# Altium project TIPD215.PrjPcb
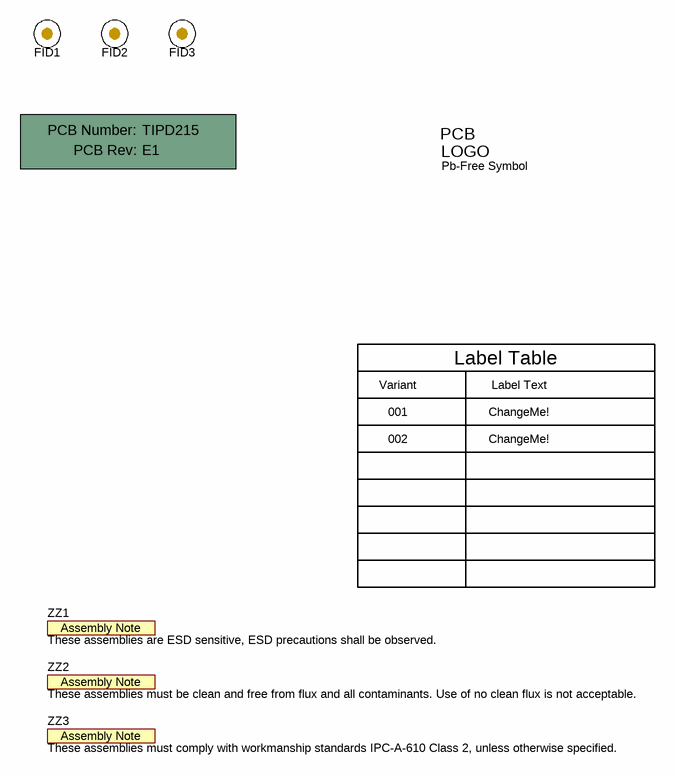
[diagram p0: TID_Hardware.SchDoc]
CopyrightYear: 2017; EVM_Orderable: N; PCB_Layout: Kevin Duke; PCB_Rev: E1; PRJ_Customer: Public Release; PRJ_Engineer: Kevin Duke; PRJ_Number: TIPD215; PRJ_Title: Less than 1W, Quad Channel, Analog Output Module with Adaptive Power Management; SCH_Rev: E1; TechSupport: http://www.ti.com/support; TID: TIPD215
3 sheets, 155 parts. Net scope: flat (ports and power ports of the same name join across sheets).
Board file: TIDPD215.PcbDoc
Sheets:
  TID_Hardware.SchDoc
  TIPD215_Device.SchDoc
  TIPD215_DAC8775SMPS.SchDoc

## Sheet TID_Hardware.SchDoc
size 431 x 279 mm; Date: Not shown in title block; ApprovedBy: Not shown in title block; CheckedBy: Not shown in title block; Author: Not shown in title block; CompanyName: Not shown in title block; Engineer: Not shown in title block; Organization: Not shown in title block; Address1: Not shown in title block; Address2: Not shown in title block; Address3: Not shown in title block; Address4: Not shown in title block; DocumentNumber: 1; Revision: Use project parameter SCH_Rev; SheetNumber: 3; SheetTotal: 3; PageSetup: Record=PageOptions¦CenterHorizontal=True¦CenterVertical=True¦PrintScale=1.00¦XCorrection=1.00¦YCorrection=1.00¦PrintKind=0¦BorderSize=5000000¦LeftOffset=0¦BottomOffset=0¦Orientation=2¦PaperLength=1000¦PaperWidth=1000¦Scale=100¦PaperSource=15¦PrintQuality=600¦MediaType=1¦DitherType=10¦PaperKind=Letter¦PrintScaleMode=1

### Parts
!PCB1  Printed Circuit Board  (value not drawn)  (mechanical)
FID1  Fiducial  [Fiducial10-20]  (value not drawn)
FID2  Fiducial  [Fiducial10-20]  (value not drawn)
FID3  Fiducial  [Fiducial10-20]  (value not drawn)
Logo2  Pb-Free Symbol  [Pb-Free_Overlay_Small]  (no BOM)
ZZ1  These assemblies are ESD sensitive, ESD precautions shall be observed.  [AssemblyNote]  (no BOM)
ZZ2  These assemblies must be clean and free from flux and all contaminants. Use of no clean flux is not acceptable.  [AssemblyNote]  (no BOM)
ZZ3  These assemblies must comply with workmanship standards IPC-A-610 Class 2, unless otherwise specified.  [AssemblyNote]  (no BOM)

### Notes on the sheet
- Variant
- Label Table
- Label Text
- 001
- 002
- ChangeMe!

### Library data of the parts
!PCB1 = PCB: Manufacturer: Any; PartNumber: TIPD215; SymbolCreator: a0412235
FID1-FID3 = Fiducial: Fiducial mark.  There is nothing to buy or mount.; SymbolCreator: codlsc
Logo2 = Pb-Free: SymbolCreator: a0412235
ZZ1-ZZ3 = AssemblyNote: SymbolCreator: codlsc

## Sheet TIPD215_Device.SchDoc
size 431 x 279 mm; Date: Not shown in title block; ApprovedBy: Not shown in title block; CheckedBy: Not shown in title block; Author: Not shown in title block; CompanyName: Not shown in title block; Engineer: Not shown in title block; Organization: Not shown in title block; Address1: Not shown in title block; Address2: Not shown in title block; Address3: Not shown in title block; Address4: Not shown in title block; DocumentNumber: 1; Revision: Use project parameter SCH_Rev; SheetNumber: 2; SheetTotal: 3; PageSetup: Record=PageOptions¦CenterHorizontal=True¦CenterVertical=True¦PrintScale=1.00¦XCorrection=1.00¦YCorrection=1.00¦PrintKind=0¦BorderSize=5000000¦LeftOffset=0¦BottomOffset=0¦Orientation=2¦PaperLength=1000¦PaperWidth=1000¦Scale=100¦PaperSource=15¦PrintQuality=600¦MediaType=1¦DitherType=10¦PaperKind=Letter¦PrintScaleMode=1
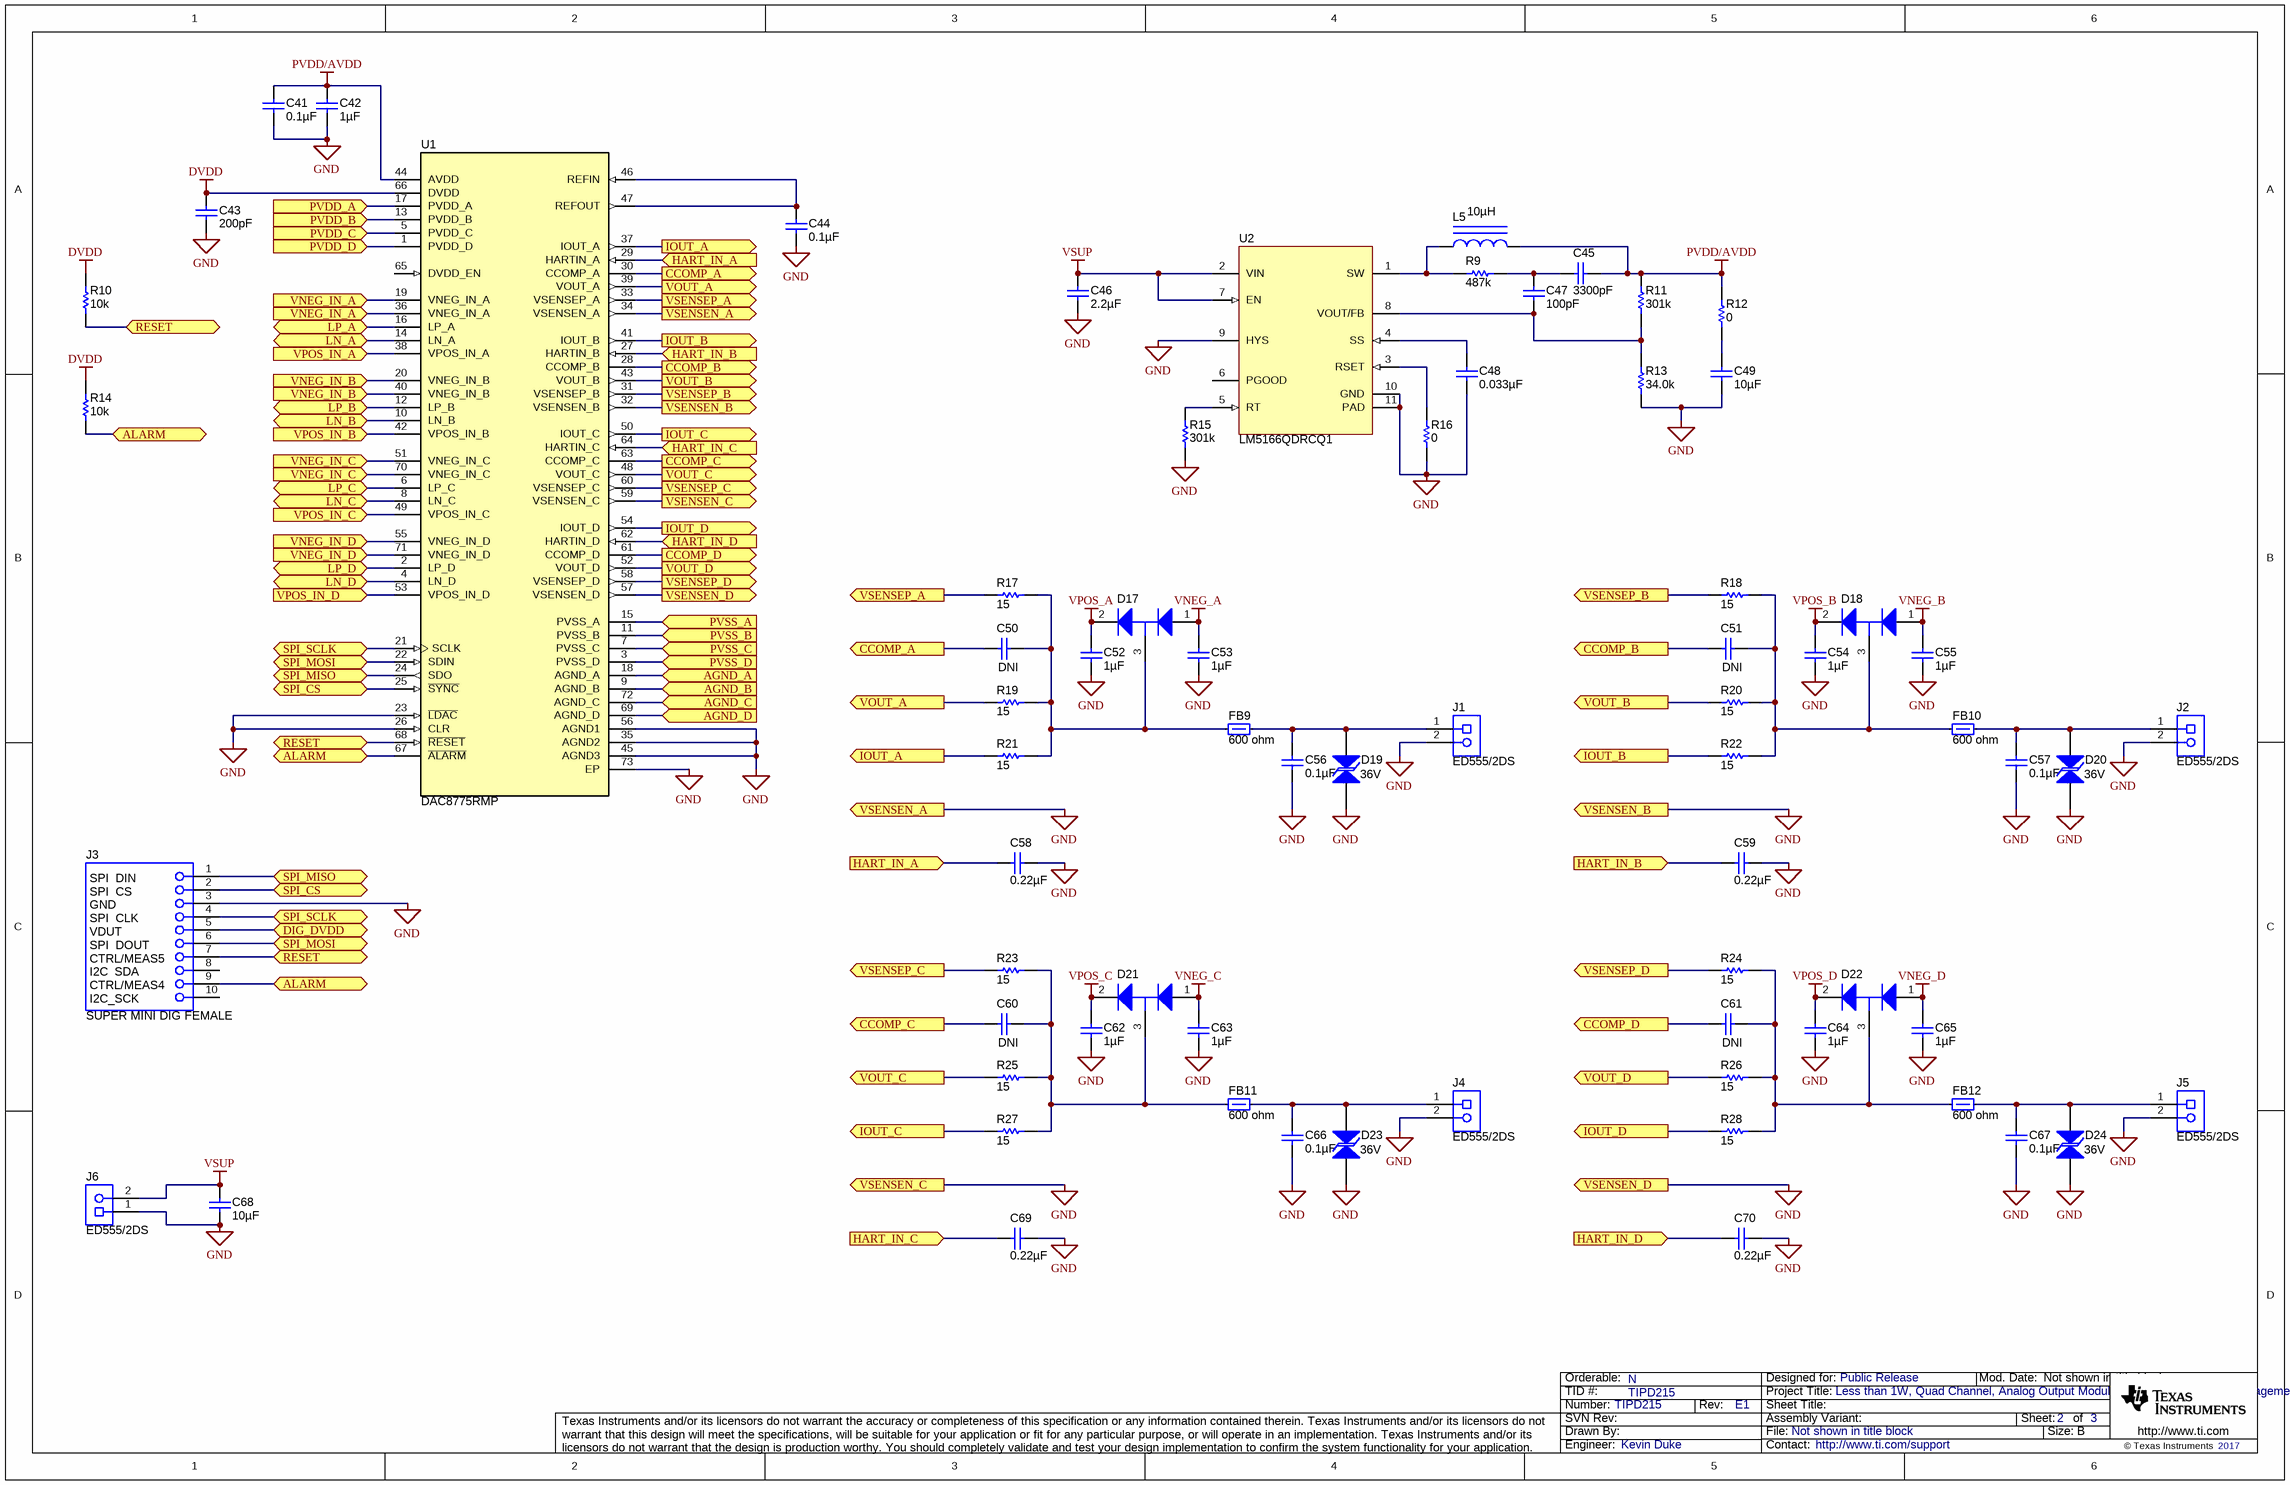
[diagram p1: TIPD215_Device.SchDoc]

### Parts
C41  ValueDisplayed: 0.1µF  [0603]  (hidden comment: GRM188R71H104KA93D)
C42  ValueDisplayed: 1µF  [0603]  (hidden comment: UMK107AB7105KA-T)
C43  ValueDisplayed: 200pF  [0603]  (hidden comment: GRM1885C1H201JA01D)
C44  ValueDisplayed: 0.1µF  [0603]  (hidden comment: GRM188R71H104KA93D)
C45  ValueDisplayed: 3300pF  [0603]  (hidden comment: 06031C332JAT2A)
C46  ValueDisplayed: 2.2µF  [1206_190]  (hidden comment: CL31B225KCHSNNE)
C47  ValueDisplayed: 100pF  [0603]  (hidden comment: GCM1885C2A101JA16D)
C48  ValueDisplayed: 0.033µF  [0603]  (hidden comment: GRM188R71H333KA61D)
C49  ValueDisplayed: 10µF  [1210_280]  (hidden comment: UMK325AB7106KM-T)
C50  DNI  [0603]
C51  DNI  [0603]
C52  ValueDisplayed: 1µF  [0603]  (hidden comment: UMK107AB7105KA-T)
C53  ValueDisplayed: 1µF  [0603]  (hidden comment: UMK107AB7105KA-T)
C54  ValueDisplayed: 1µF  [0603]  (hidden comment: UMK107AB7105KA-T)
C55  ValueDisplayed: 1µF  [0603]  (hidden comment: UMK107AB7105KA-T)
C56  ValueDisplayed: 0.1µF  [0603]  (hidden comment: GRM188R71H104KA93D)
C57  ValueDisplayed: 0.1µF  [0603]  (hidden comment: GRM188R71H104KA93D)
C58  ValueDisplayed: 0.22µF  [0603]  (hidden comment: C1608X7R1H224K080AB)
C59  ValueDisplayed: 0.22µF  [0603]  (hidden comment: C1608X7R1H224K080AB)
C60  DNI  [0603]
C61  DNI  [0603]
C62  ValueDisplayed: 1µF  [0603]  (hidden comment: UMK107AB7105KA-T)
C63  ValueDisplayed: 1µF  [0603]  (hidden comment: UMK107AB7105KA-T)
C64  ValueDisplayed: 1µF  [0603]  (hidden comment: UMK107AB7105KA-T)
C65  ValueDisplayed: 1µF  [0603]  (hidden comment: UMK107AB7105KA-T)
C66  ValueDisplayed: 0.1µF  [0603]  (hidden comment: GRM188R71H104KA93D)
C67  ValueDisplayed: 0.1µF  [0603]  (hidden comment: GRM188R71H104KA93D)
C68  ValueDisplayed: 10µF  [1210_280]  (hidden comment: UMK325AB7106KM-T)
C69  ValueDisplayed: 0.22µF  [0603]  (hidden comment: C1608X7R1H224K080AB)
C70  ValueDisplayed: 0.22µF  [0603]  (hidden comment: C1608X7R1H224K080AB)
D17  BAV99-7-F  [SOT-23]  (value not drawn)
D18  BAV99-7-F  [SOT-23]  (value not drawn)
D19  value 36V  [SOD-323-Bi]  (hidden comment: CDSOD323-T36SC)
D20  value 36V  [SOD-323-Bi]  (hidden comment: CDSOD323-T36SC)
D21  BAV99-7-F  [SOT-23]  (value not drawn)
D22  BAV99-7-F  [SOT-23]  (value not drawn)
D23  value 36V  [SOD-323-Bi]  (hidden comment: CDSOD323-T36SC)
D24  value 36V  [SOD-323-Bi]  (hidden comment: CDSOD323-T36SC)
FB9  value 600 ohm  [1210_280]  (hidden comment: FBMH3225HM601NT)
FB10  value 600 ohm  [1210_280]  (hidden comment: FBMH3225HM601NT)
FB11  value 600 ohm  [1210_280]  (hidden comment: FBMH3225HM601NT)
FB12  value 600 ohm  [1210_280]  (hidden comment: FBMH3225HM601NT)
J1  ED555/2DS  [TERM_BLK_ED555-2DS]
J2  ED555/2DS  [TERM_BLK_ED555-2DS]
J3  SUPER MINI DIG FEMALE  [CONN_851-43-010-20-001000]
J4  ED555/2DS  [TERM_BLK_ED555-2DS]
J5  ED555/2DS  [TERM_BLK_ED555-2DS]
J6  ED555/2DS  [TERM_BLK_ED555-2DS]
L5  ValueDisplayed: 10µH  [WE-LQS_6045]  (hidden comment: 74404064100)
R9  ValueDisplayed: 487k  [0603]  (hidden comment: CRCW0603487KFKEA)
R10  value 10k  [0603]  (hidden comment: CRCW060310K0JNEA)
R11  ValueDisplayed: 301k  [0603]  (hidden comment: CRCW0603301KFKEA)
R12  ValueDisplayed: 0  [0603]  (hidden comment: CRCW06030000Z0EA)
R13  ValueDisplayed: 34.0k  [0603]  (hidden comment: CRCW060334K0FKEA)
R14  value 10k  [0603]  (hidden comment: CRCW060310K0JNEA)
R15  ValueDisplayed: 301k  [0603]  (hidden comment: CRCW0603301KFKEA)
R16  ValueDisplayed: 0  [0603]  (hidden comment: CRCW06030000Z0EA)
R17  value 15  [0603]  (hidden comment: CRCW060315R0JNEA)
R18  value 15  [0603]  (hidden comment: CRCW060315R0JNEA)
R19  value 15  [0603]  (hidden comment: CRCW060315R0JNEA)
R20  value 15  [0603]  (hidden comment: CRCW060315R0JNEA)
R21  value 15  [0603]  (hidden comment: CRCW060315R0JNEA)
R22  value 15  [0603]  (hidden comment: CRCW060315R0JNEA)
R23  value 15  [0603]  (hidden comment: CRCW060315R0JNEA)
R24  value 15  [0603]  (hidden comment: CRCW060315R0JNEA)
R25  value 15  [0603]  (hidden comment: CRCW060315R0JNEA)
R26  value 15  [0603]  (hidden comment: CRCW060315R0JNEA)
R27  value 15  [0603]  (hidden comment: CRCW060315R0JNEA)
R28  value 15  [0603]  (hidden comment: CRCW060315R0JNEA)
U1  DAC8775RMP  [RMP0072A]
U2  LM5166QDRCQ1  [DRC0010J]

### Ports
AGND_A (in), AGND_B (in), AGND_C (in), AGND_D (in), ALARM, CCOMP_A (out), CCOMP_B (out), CCOMP_C (out), CCOMP_D (out), DIG_DVDD, HART_IN_A (in), HART_IN_B (in), HART_IN_C (in), HART_IN_D (in), IOUT_A (out), IOUT_B (out), IOUT_C (out), IOUT_D (out), LN_A (bidir), LN_B (bidir), LN_C (bidir), LN_D (bidir), LP_A (bidir), LP_B (bidir), LP_C (bidir), LP_D (bidir), PVDD_A (in), PVDD_B (in), PVDD_C (in), PVDD_D (in), PVSS_A (in), PVSS_B (in), PVSS_C (in), PVSS_D (in), RESET, SPI_CS, SPI_MISO, SPI_MOSI, SPI_SCLK, VNEG_IN_A (in), VNEG_IN_B (in), VNEG_IN_C (in), VNEG_IN_D (in), VOUT_A (out), VOUT_B (out), VOUT_C (out), VOUT_D (out), VPOS_IN_A (in), VPOS_IN_B (in), VPOS_IN_C (in), VPOS_IN_D (in), VSENSEN_A (out), VSENSEN_B (out), VSENSEN_C (out), VSENSEN_D (out), VSENSEP_A (out), VSENSEP_B (out), VSENSEP_C (out), VSENSEP_D (out)

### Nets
DVDD: C43.1 R10.2 R14.2 U1.66(DVDD)
GND: C41.1 C42.1 C43.2 C44.2 C46.2 C48.2 C49.2 C52.1 C53.1 C54.1 C55.1 C56.2 C57.2 C58.1 C59.1 C62.1 C63.1 C64.1 C65.1 C66.2 C67.2 C68.2 C69.1 C70.1 D19.1 D20.1 D23.1 D24.1 J1.2 J2.2 J3.3 J4.2 J5.2 J6.1 R13.1 R15.1 R16.1 U1.3(PVSS_D) U1.7(PVSS_C) U1.9(AGND_B) U1.11(PVSS_B) U1.15(PVSS_A) U1.18(AGND_A) U1.23(~{LDAC}) U1.26(CLR) U1.32(VSENSEN_B) U1.34(VSENSEN_A) U1.35(AGND2) U1.45(AGND3) U1.56(AGND1) U1.57(VSENSEN_D) U1.59(VSENSEN_C) U1.69(AGND_D) U1.72(AGND_C) U1.73(EP) U2.9(HYS) U2.10(GND) U2.11(PAD) ; port VSENSEN_A, port VSENSEN_B, port VSENSEN_C, port VSENSEN_D, port AGND_A, port PVSS_A, port AGND_B, port PVSS_B, port AGND_C, port PVSS_C, port AGND_D, port PVSS_D
PVDD/AVDD: C41.2 C42.2 C45.1 L5.2 R11.2 R12.2 U1.1(PVDD_D) U1.5(PVDD_C) U1.13(PVDD_B) U1.17(PVDD_A) U1.44(AVDD) ; port PVDD_A, port PVDD_B, port PVDD_C, port PVDD_D
VNEG_A: C53.2 D17.1(A) U1.19(VNEG_IN_A) U1.36(VNEG_IN_A) ; port VNEG_IN_A
VNEG_B: C55.2 D18.1(A) U1.20(VNEG_IN_B) U1.40(VNEG_IN_B) ; port VNEG_IN_B
VNEG_C: C63.2 D21.1(A) U1.51(VNEG_IN_C) U1.70(VNEG_IN_C) ; port VNEG_IN_C
VNEG_D: C65.2 D22.1(A) U1.55(VNEG_IN_D) U1.71(VNEG_IN_D) ; port VNEG_IN_D
VPOS_A: C52.2 D17.2(K) U1.38(VPOS_IN_A) ; port VPOS_IN_A
VPOS_B: C54.2 D18.2(K) U1.42(VPOS_IN_B) ; port VPOS_IN_B
VPOS_C: C62.2 D21.2(K) U1.49(VPOS_IN_C) ; port VPOS_IN_C
VPOS_D: C64.2 D22.2(K) U1.53(VPOS_IN_D) ; port VPOS_IN_D
VSUP: C46.1 C68.1 J6.2 U2.2(VIN) U2.7(EN)
ALARM: J3.9 R14.1 U1.67(~{ALARM}) ; port ALARM
CCOMP_A: C50.2 U1.30(CCOMP_A) ; port CCOMP_A
CCOMP_B: C51.2 U1.28(CCOMP_B) ; port CCOMP_B
CCOMP_C: C60.2 U1.63(CCOMP_C) ; port CCOMP_C
CCOMP_D: C61.2 U1.61(CCOMP_D) ; port CCOMP_D
DIG_DVDD: J3.5 ; port DIG_DVDD
HART_IN_A: C58.2 U1.29(HARTIN_A) ; port HART_IN_A
HART_IN_B: C59.2 U1.27(HARTIN_B) ; port HART_IN_B
HART_IN_C: C69.2 U1.64(HARTIN_C) ; port HART_IN_C
HART_IN_D: C70.2 U1.62(HARTIN_D) ; port HART_IN_D
IOUT_A: R21.1 U1.37(IOUT_A) ; port IOUT_A
IOUT_B: R22.1 U1.41(IOUT_B) ; port IOUT_B
IOUT_C: R27.1 U1.50(IOUT_C) ; port IOUT_C
IOUT_D: R28.1 U1.54(IOUT_D) ; port IOUT_D
LN_A: U1.14(LN_A) ; port LN_A
LN_B: U1.10(LN_B) ; port LN_B
LN_C: U1.8(LN_C) ; port LN_C
LN_D: U1.4(LN_D) ; port LN_D
LP_A: U1.16(LP_A) ; port LP_A
LP_B: U1.12(LP_B) ; port LP_B
LP_C: U1.6(LP_C) ; port LP_C
LP_D: U1.2(LP_D) ; port LP_D
RESET: J3.7 R10.1 U1.68(~{RESET}) ; port RESET
SPI_CS: J3.2 U1.25(~{SYNC}) ; port SPI_CS
SPI_MISO: J3.1 U1.24(SDO) ; port SPI_MISO
SPI_MOSI: J3.6 U1.22(SDIN) ; port SPI_MOSI
SPI_SCLK: J3.4 U1.21(SCLK) ; port SPI_SCLK
VOUT_A: R19.1 U1.39(VOUT_A) ; port VOUT_A
VOUT_B: R20.1 U1.43(VOUT_B) ; port VOUT_B
VOUT_C: R25.1 U1.48(VOUT_C) ; port VOUT_C
VOUT_D: R26.1 U1.52(VOUT_D) ; port VOUT_D
VSENSEP_A: R17.1 U1.33(VSENSEP_A) ; port VSENSEP_A
VSENSEP_B: R18.1 U1.31(VSENSEP_B) ; port VSENSEP_B
VSENSEP_C: R23.1 U1.60(VSENSEP_C) ; port VSENSEP_C
VSENSEP_D: R24.1 U1.58(VSENSEP_D) ; port VSENSEP_D
NetC44_1: C44.1 U1.46(REFIN) U1.47(REFOUT)
NetC45_2: C45.2 C47.1 R9.2
NetC47_2: C47.2 R11.1 R13.2 U2.8(VOUT/FB)
NetC48_1: C48.1 U2.4(SS)
NetC49_1: C49.1 R12.1
NetC50_1: C50.1 D17.3(C) FB9.1 R17.2 R19.2 R21.2
NetC51_1: C51.1 D18.3(C) FB10.1 R18.2 R20.2 R22.2
NetC56_1: C56.1 D19.2 FB9.2 J1.1
NetC57_1: C57.1 D20.2 FB10.2 J2.1
NetC60_1: C60.1 D21.3(C) FB11.1 R23.2 R25.2 R27.2
NetC61_1: C61.1 D22.3(C) FB12.1 R24.2 R26.2 R28.2
NetC66_1: C66.1 D23.2 FB11.2 J4.1
NetC67_1: C67.1 D24.2 FB12.2 J5.1
NetL5_1: L5.1 R9.1 U2.1(SW)
NetR15_2: R15.2 U2.5(RT)
NetR16_2: R16.2 U2.3(RSET)

Not connected (* = marked no-connect by the designer): J3 8 10; U1 65(DVDD_EN); U2 6(PGOOD)

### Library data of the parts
C41 C44 C56 C57 C66 C67 = GRM188R71H104KA93D: CAP, CERM, 0.1uF, 50V, +/-10%, X7R, 0603; Manufacturer: MuRata; Polarized: N; CompType: Capacitor; U/M: EA; Cap_F: 0.0000001; Tolerance_%: 10; Value1: Unknown; VDC_V: 50; TaMin_C: -55; TaMax_C: 125
C42 C52-C55 C62-C65 = UMK107AB7105KA-T: CAP, CERM, 1uF, 50V, +/-10%, X7R, 0603; Manufacturer: Taiyo Yuden; Polarized: N; CompType: Capacitor; U/M: EA; Cap_F: 0.000001; Tolerance_%: 10; Value1: Unknown; VDC_V: 50; TaMin_C: -55; TaMax_C: 125
C43 = GRM1885C1H201JA01D: CAP, CERM, 200pF, 50V, +/-5%, C0G/NP0, 0603; Manufacturer: MuRata; Polarized: N; CompType: Capacitor; U/M: EA; Cap_F: 0.0000000002; Tolerance_%: 5; Value1: Unknown; VDC_V: 50; TaMin_C: -55; TaMax_C: 125
C45 = 06031C332JAT2A: CAP, CERM, 3300 pF, 100 V, +/- 5%, X7R, 0603; Manufacturer: AVX; Polarized: N; CompType: Capacitor; Value: 3300pF; U/M: EA; Cap_F: 0.0000000033; Tolerance_%: 5; ESR_ohm: 0.159; Value1: 0.159 ohm; VDC_V: 100; Value2: 100V; TaMin_C: -55; TaMax_C: 125; SizeArea_mm2: 1.28; SizeAreaWB_mm2: 4.68; SizeX_mm: 1.6; SizeY_mm: 0.8; SizeZ_mm: 1; AEC Category: Q200
C46 = CL31B225KCHSNNE: CAP, CERM, 2.2 µF, 100 V, +/- 10%, X7R, 1206_190; Manufacturer: Samsung Electro-Mechanics; Polarized: N; CompType: Capacitor; Value: 2.2uF; U/M: EA; Cap_F: 0.0000022; Tolerance_%: 10; Value1: Unknown; VDC_V: 100; Value2: 100V; TaMin_C: -55; TaMax_C: 125; Cap_Case: 1206; SizeArea_mm2: 5.12; SizeAreaWB_mm2: 10.92; SizeX_mm: 3.2; SizeY_mm: 1.6; SizeZ_mm: 1.9; AEC Category: Q200
C47 = GCM1885C2A101JA16D: CAP, CERM, 100 pF, 100 V, +/- 5%, C0G/NP0, AEC-Q200 Grade 1, 0603; Manufacturer: MuRata; Polarized: N; CompType: Capacitor; Value: 100pF; U/M: EA; Cap_F: 0.0000000001; Tolerance_%: 5; Value1: Unknown; VDC_V: 100; Value2: 100V; TaMin_C: -55; TaMax_C: 125; SizeArea_mm2: 1.28; SizeAreaWB_mm2: 4.68; SizeX_mm: 1.6; SizeY_mm: 0.8; SizeZ_mm: 1; AEC Category: Q200; AEC Qualified: Y
C48 = GRM188R71H333KA61D: CAP, CERM, 0.033 µF, 50 V, +/- 10%, X7R, 0603; Manufacturer: MuRata; Polarized: N; CompType: Capacitor; Value: 0.033uF; U/M: EA; Cap_F: 0.000000033; Tolerance_%: 10; Value1: Unknown; VDC_V: 50; Value2: 50V; TaMin_C: -55; TaMax_C: 125; SizeArea_mm2: 1.28; SizeAreaWB_mm2: 4.68; SizeX_mm: 1.6; SizeY_mm: 0.8; SizeZ_mm: 1; AEC Category: Q200
C49 C68 = UMK325AB7106KM-T: CAP, CERM, 10 µF, 50 V, +/- 10%, X7R, 1210; Manufacturer: Taiyo Yuden; Polarized: N; CompType: Capacitor; Value: 10uF; U/M: EA; Cap_F: 0.00001; Tolerance_%: 10; Value1: Unknown; VDC_V: 50; Value2: 50V; TaMin_C: -55; TaMax_C: 125; Cap_Case: 1210; SizeArea_mm2: 8; SizeAreaWB_mm2: 14.7; SizeX_mm: 3.2; SizeY_mm: 2.5; SizeZ_mm: 2.8; AEC Category: Q200
C50 C51 C60 C61 = GRM1885C1H222JA01D
C58 C59 C69 C70 = C1608X7R1H224K080AB: CAP, CERM, 0.22 µF, 50 V, +/- 10%, X7R, 0603; Manufacturer: TDK; Polarized: N; CompType: Capacitor; Value: 0.22uF; U/M: EA; Cap_F: 0.00000022; Tolerance_%: 10; ESR_ohm: 0.021699; Value1: 0.021699 ohm; VDC_V: 50; Value2: 50V; IRMS_A: 1.12496; TaMin_C: -55; TaMax_C: 125; SizeArea_mm2: 1.28; SizeAreaWB_mm2: 4.68; SizeX_mm: 1.6; SizeY_mm: 0.8; SizeZ_mm: 1; AEC Category: Q200
D17 D18 D21 D22 = BAV99-7-F: Diode, Switching, 75V, 0.3A, SOT-23; Manufacturer: Diodes Inc.; U/M: EA; Vf_V: 1.25; Value2: 1.25V; Io_A: 0.3; Vr_V: 75; TJmax_C: 150; RJC_CperW: 357
D19 D20 D23 D24 = CDSOD323-T36SC: Diode, TVS, Bi, 36V, 400W, SOD323, 2-Leads, Body 1.9x1.45mm, No Polarity Mark; Manufacturer: Bourns; U/M: EA; Power_W: 400; Vr_V: 36
FB9-FB12 = FBMH3225HM601NT: Ferrite Bead, 600 ohm @ 100 MHz, 3 A, 1210; Manufacturer: Taiyo Yuden; Imax_A: 3; DCR_ohm: 0.042; Value1: 0.042 ohm; Value2: 3A; ZTyp@100MHz_Ohm: 600
J1 J2 J4-J6 = ED555/2DS: Terminal Block, 3.5mm Pitch, 2x1, TH; Manufacturer: On-Shore Technology; SymbolCreator: a0412235; Pitch_mm: 3.5; Gender: Female; Shrouded: N; Row_Count: 1; ContactFinish: Brass; Current_A: 6; Voltage_V: 150; Cert_CULUS: Y
J3 = 851-43-010-20-001000: Receptacle, 50mil 10x1, R/A, TH; Manufacturer: Mill-Max; SymbolCreator: a0411947; U/M: EA
L5 = 74404064100: Inductor, Wirewound, Ferrite, 10 µH, 2.45 A, 0.048 ohm, SMD; Manufacturer: Wurth Elektronik; Value: 10uH; Ind_H: 10.0E-6; Imax_A: 2.45; Irms: 2.45A @ 40C rise; Isat: 3.5A @ 30% inductance drop; DCR_ohm: 0.048; Value2: 2.45A; AEC Category: Q200
R9 = CRCW0603487KFKEA: RES, 487 k, 1%, 0.1 W, 0603; Manufacturer: Vishay-Dale; CompType: Resistor; Value: 487k; Res_ohm: 487000; Tolerance_%: 1; Power_W: 0.1; Value2: 0.1W; VDC_V: 75; TempCo: 100 ppm/C; SizeArea_mm2: 1.28; SizeX_mm: 1.6; SizeY_mm: 0.8; EIA_Code: E96; U/M: EA; AEC Category: Q200
R10 R14 = CRCW060310K0JNEA: RES, 10k ohm, 5%, 0.1W, 0603; Manufacturer: Vishay-Dale; CompType: Resistor; Res_ohm: 10000; Value_Code: 10k0; Tolerance_%: 5; Power_W: 0.1; VDC_V: 75; TempCo: 200 ppm/C; EIA_Code: E24; U/M: EA
R11 R15 = CRCW0603301KFKEA: RES, 301 k, 1%, 0.1 W, 0603; Manufacturer: Vishay-Dale; CompType: Resistor; Value: 301k; Res_ohm: 301000; Tolerance_%: 1; Power_W: 0.1; Value2: 0.1W; VDC_V: 75; TempCo: 100 ppm/C; SizeArea_mm2: 1.28; SizeX_mm: 1.6; SizeY_mm: 0.8; EIA_Code: E96; U/M: EA; AEC Category: Q200
R12 R16 = CRCW06030000Z0EA: RES, 0, 5%, 0.1 W, 0603; Manufacturer: Vishay-Dale; CompType: Resistor; Value: 0; Value_Code: 0000; Tolerance_%: 5; Power_W: 0.1; Value2: 0.1W; VDC_V: 75; TempCo: 200 ppm/C; SizeArea_mm2: 1.28; SizeX_mm: 1.6; SizeY_mm: 0.8; SizeZ_mm: 1; EIA_Code: E24; U/M: EA; AEC Category: Q200
R13 = CRCW060334K0FKEA: RES, 34.0 k, 1%, 0.1 W, 0603; Manufacturer: Vishay-Dale; CompType: Resistor; Value: 34.0k; Res_ohm: 34000; Value_Code: 34k0; Tolerance_%: 1; Power_W: 0.1; Value2: 0.1W; VDC_V: 75; TempCo: 100 ppm/C; SizeArea_mm2: 1.28; SizeX_mm: 1.6; SizeY_mm: 0.8; EIA_Code: E96; U/M: EA; AEC Category: Q200
R17-R28 = CRCW060315R0JNEA: RES, 15 ohm, 5%, 0.1W, 0603; Manufacturer: Vishay-Dale; CompType: Resistor; Value_Code: 15R0; Tolerance_%: 5; Power_W: 0.1; VDC_V: 75; TempCo: 200 ppm/C; EIA_Code: E24; U/M: EA
U1 = DAC8775RMP: Quad-Channel, 16-Bit Programmable Current Output and Voltage Output Digital-to-Analog Converter with Adaptive Power Management, RMP0072A; Manufacturer: Texas Instruments; SymbolCreator: Altium; SizeArea_mm2: 100; SizeAreaWB_mm2: 144; SizeX_mm: 10; SizeZ_mm: 1; CompType: IC; U/M: EA
U2 = LM5166QDRCQ1: 3.5-V to 65-V Input, 500-mA Output, Ultra-Low Quiescent Synchronous Step-Down DC/DC Voltage Regulator, DRC0010J; Manufacturer: Texas Instruments; SymbolCreator: a0411947; SizeArea_mm2: 9; SizeAreaWB_mm2: 16; SizeX_mm: 3; SizeZ_mm: 1; CompType: IC; U/M: EA

## Sheet TIPD215_DAC8775SMPS.SchDoc
size 431 x 279 mm; Date: Not shown in title block; ApprovedBy: Not shown in title block; CheckedBy: Not shown in title block; Author: Not shown in title block; CompanyName: Not shown in title block; Engineer: Not shown in title block; Organization: Not shown in title block; Address1: Not shown in title block; Address2: Not shown in title block; Address3: Not shown in title block; Address4: Not shown in title block; DocumentNumber: 1; Revision: Use project parameter SCH_Rev; SheetNumber: 2; SheetTotal: 3; PageSetup: Record=PageOptions¦CenterHorizontal=True¦CenterVertical=True¦PrintScale=1.00¦XCorrection=1.00¦YCorrection=1.00¦PrintKind=0¦BorderSize=5000000¦LeftOffset=0¦BottomOffset=0¦Orientation=2¦PaperLength=1000¦PaperWidth=1000¦Scale=100¦PaperSource=15¦PrintQuality=600¦MediaType=1¦DitherType=10¦PaperKind=Letter¦PrintScaleMode=1
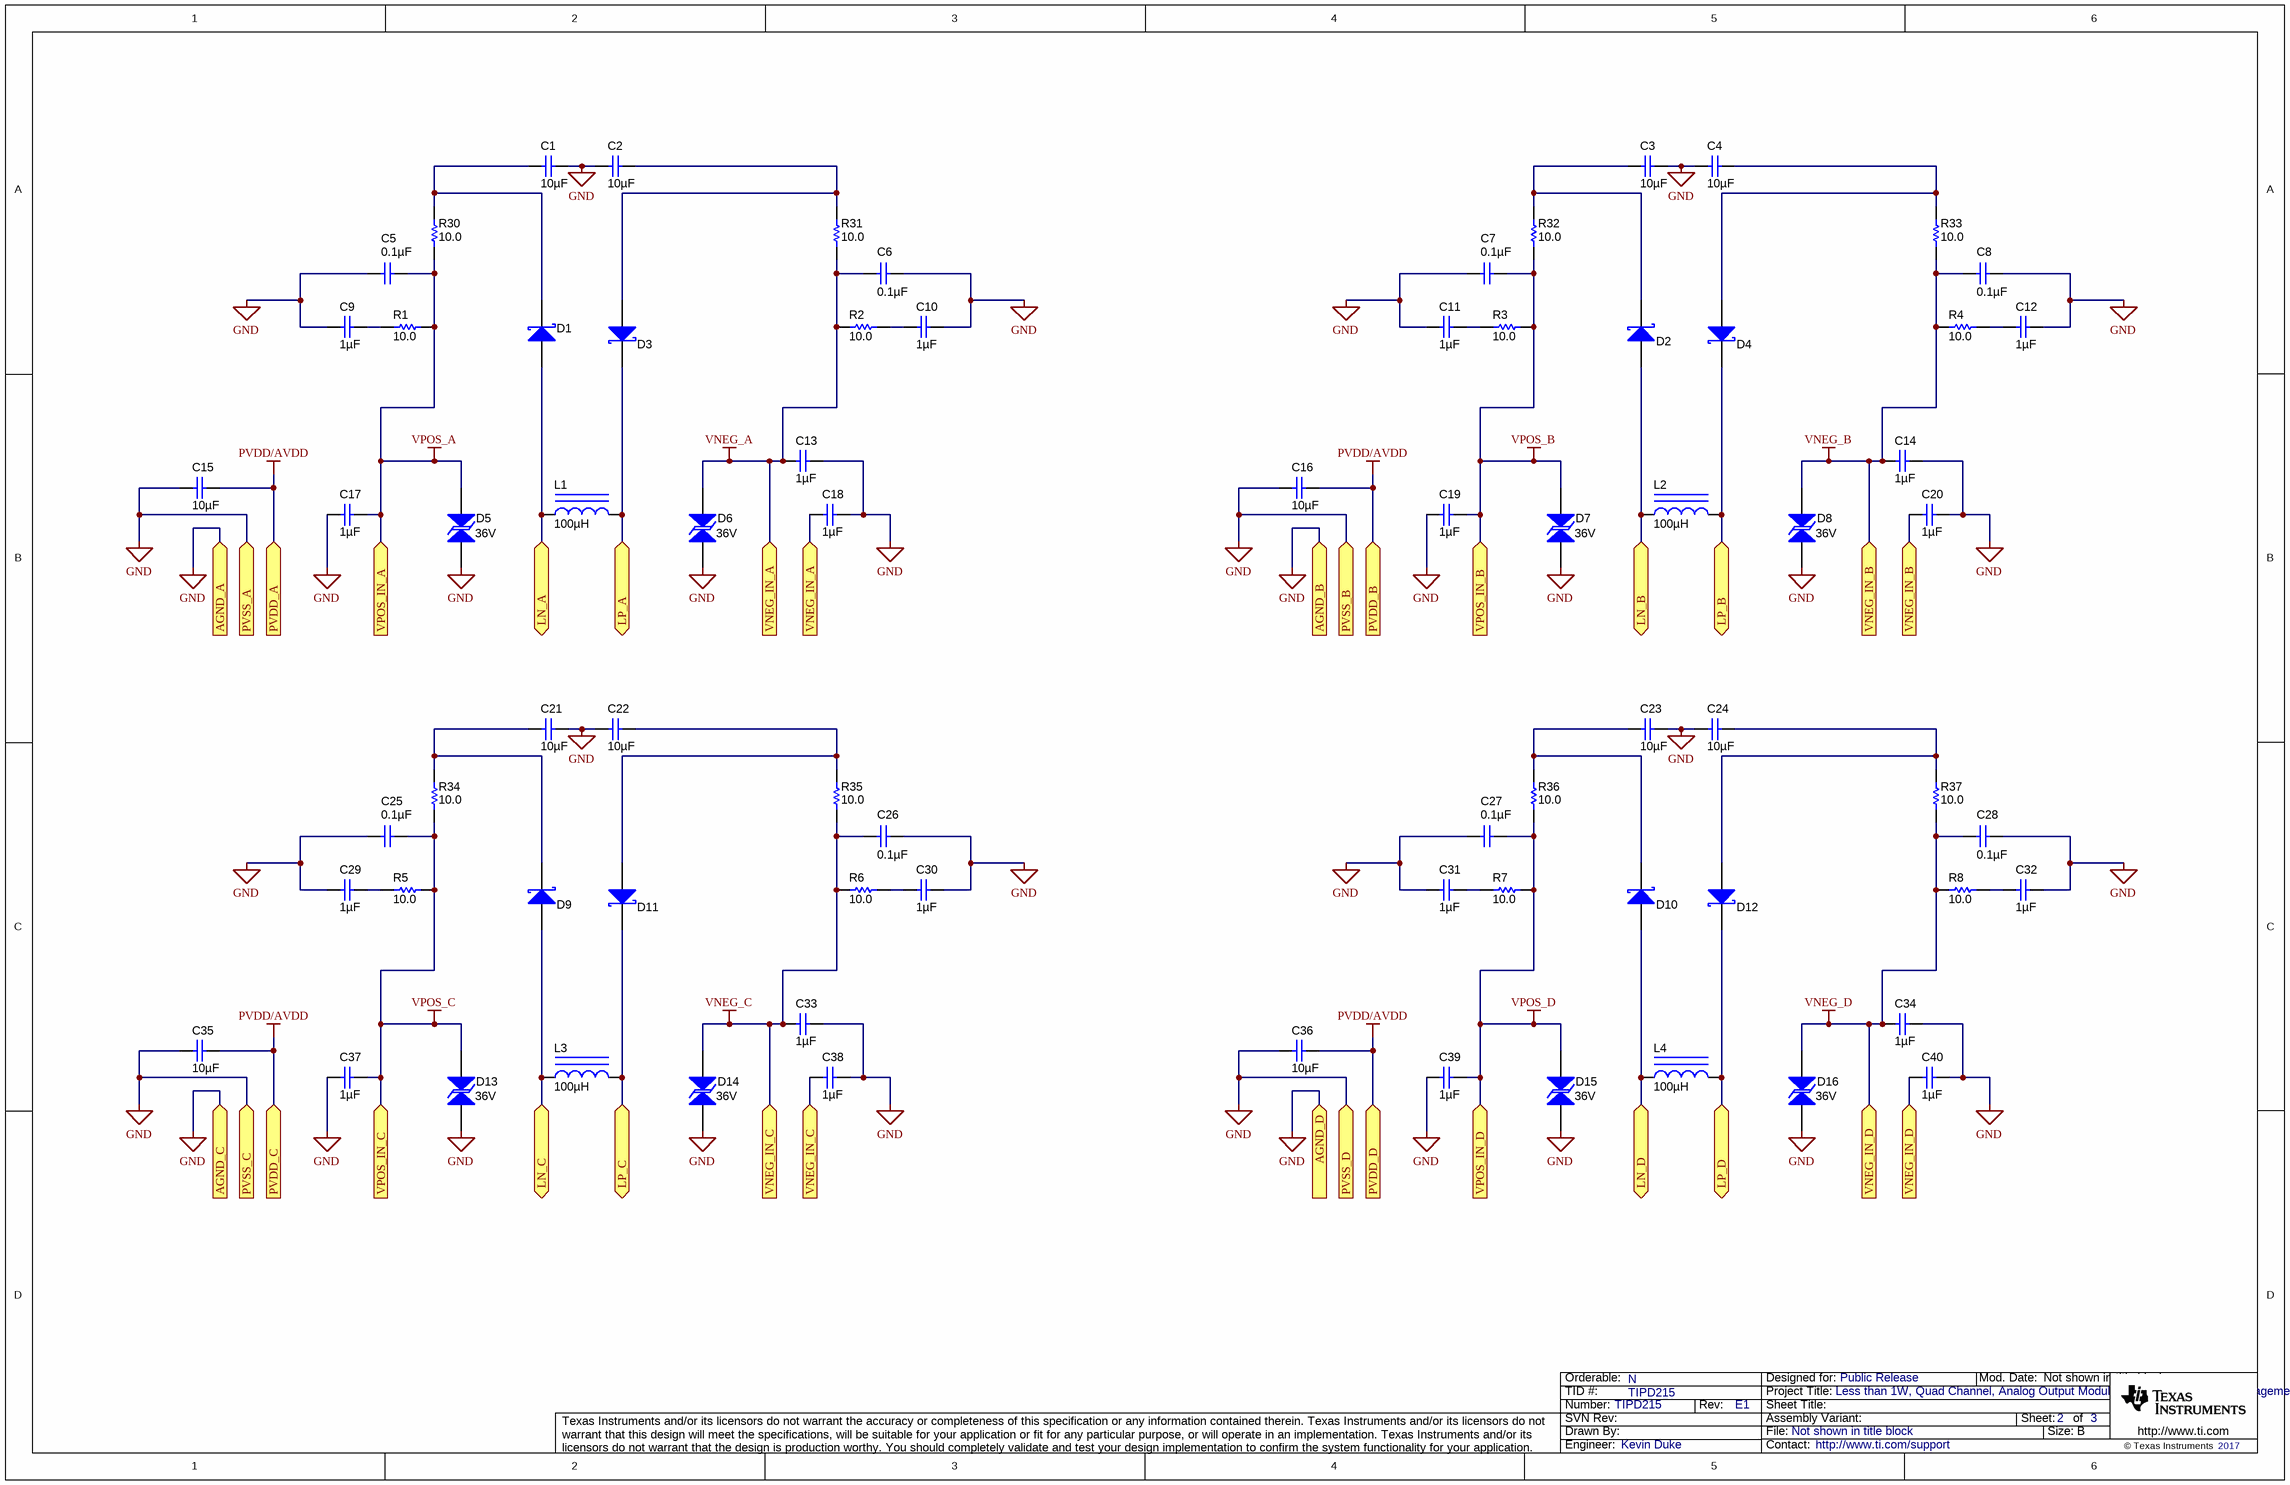
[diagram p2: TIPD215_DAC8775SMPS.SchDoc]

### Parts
C1  ValueDisplayed: 10µF  [1210_280]  (hidden comment: UMK325AB7106KM-T)
C2  ValueDisplayed: 10µF  [1210_280]  (hidden comment: UMK325AB7106KM-T)
C3  ValueDisplayed: 10µF  [1210_280]  (hidden comment: UMK325AB7106KM-T)
C4  ValueDisplayed: 10µF  [1210_280]  (hidden comment: UMK325AB7106KM-T)
C5  ValueDisplayed: 0.1µF  [0603]  (hidden comment: GRM188R71H104KA93D)
C6  ValueDisplayed: 0.1µF  [0603]  (hidden comment: GRM188R71H104KA93D)
C7  ValueDisplayed: 0.1µF  [0603]  (hidden comment: GRM188R71H104KA93D)
C8  ValueDisplayed: 0.1µF  [0603]  (hidden comment: GRM188R71H104KA93D)
C9  ValueDisplayed: 1µF  [0603]  (hidden comment: UMK107AB7105KA-T)
C10  ValueDisplayed: 1µF  [0603]  (hidden comment: UMK107AB7105KA-T)
C11  ValueDisplayed: 1µF  [0603]  (hidden comment: UMK107AB7105KA-T)
C12  ValueDisplayed: 1µF  [0603]  (hidden comment: UMK107AB7105KA-T)
C13  ValueDisplayed: 1µF  [0603]  (hidden comment: UMK107AB7105KA-T)
C14  ValueDisplayed: 1µF  [0603]  (hidden comment: UMK107AB7105KA-T)
C15  ValueDisplayed: 10µF  [1210_280]  (hidden comment: UMK325AB7106KM-T)
C16  ValueDisplayed: 10µF  [1210_280]  (hidden comment: UMK325AB7106KM-T)
C17  ValueDisplayed: 1µF  [0603]  (hidden comment: UMK107AB7105KA-T)
C18  ValueDisplayed: 1µF  [0603]  (hidden comment: UMK107AB7105KA-T)
C19  ValueDisplayed: 1µF  [0603]  (hidden comment: UMK107AB7105KA-T)
C20  ValueDisplayed: 1µF  [0603]  (hidden comment: UMK107AB7105KA-T)
C21  ValueDisplayed: 10µF  [1210_280]  (hidden comment: UMK325AB7106KM-T)
C22  ValueDisplayed: 10µF  [1210_280]  (hidden comment: UMK325AB7106KM-T)
C23  ValueDisplayed: 10µF  [1210_280]  (hidden comment: UMK325AB7106KM-T)
C24  ValueDisplayed: 10µF  [1210_280]  (hidden comment: UMK325AB7106KM-T)
C25  ValueDisplayed: 0.1µF  [0603]  (hidden comment: GRM188R71H104KA93D)
C26  ValueDisplayed: 0.1µF  [0603]  (hidden comment: GRM188R71H104KA93D)
C27  ValueDisplayed: 0.1µF  [0603]  (hidden comment: GRM188R71H104KA93D)
C28  ValueDisplayed: 0.1µF  [0603]  (hidden comment: GRM188R71H104KA93D)
C29  ValueDisplayed: 1µF  [0603]  (hidden comment: UMK107AB7105KA-T)
C30  ValueDisplayed: 1µF  [0603]  (hidden comment: UMK107AB7105KA-T)
C31  ValueDisplayed: 1µF  [0603]  (hidden comment: UMK107AB7105KA-T)
C32  ValueDisplayed: 1µF  [0603]  (hidden comment: UMK107AB7105KA-T)
C33  ValueDisplayed: 1µF  [0603]  (hidden comment: UMK107AB7105KA-T)
C34  ValueDisplayed: 1µF  [0603]  (hidden comment: UMK107AB7105KA-T)
C35  ValueDisplayed: 10µF  [1210_280]  (hidden comment: UMK325AB7106KM-T)
C36  ValueDisplayed: 10µF  [1210_280]  (hidden comment: UMK325AB7106KM-T)
C37  ValueDisplayed: 1µF  [0603]  (hidden comment: UMK107AB7105KA-T)
C38  ValueDisplayed: 1µF  [0603]  (hidden comment: UMK107AB7105KA-T)
C39  ValueDisplayed: 1µF  [0603]  (hidden comment: UMK107AB7105KA-T)
C40  ValueDisplayed: 1µF  [0603]  (hidden comment: UMK107AB7105KA-T)
D1  MBRX160-TP  [SOD-123]  (value not drawn)
D2  MBRX160-TP  [SOD-123]  (value not drawn)
D3  MBRX160-TP  [SOD-123]  (value not drawn)
D4  MBRX160-TP  [SOD-123]  (value not drawn)
D5  value 36V  [SOD-323-Bi]  (hidden comment: CDSOD323-T36SC)
D6  value 36V  [SOD-323-Bi]  (hidden comment: CDSOD323-T36SC)
D7  value 36V  [SOD-323-Bi]  (hidden comment: CDSOD323-T36SC)
D8  value 36V  [SOD-323-Bi]  (hidden comment: CDSOD323-T36SC)
D9  MBRX160-TP  [SOD-123]  (value not drawn)
D10  MBRX160-TP  [SOD-123]  (value not drawn)
D11  MBRX160-TP  [SOD-123]  (value not drawn)
D12  MBRX160-TP  [SOD-123]  (value not drawn)
D13  value 36V  [SOD-323-Bi]  (hidden comment: CDSOD323-T36SC)
D14  value 36V  [SOD-323-Bi]  (hidden comment: CDSOD323-T36SC)
D15  value 36V  [SOD-323-Bi]  (hidden comment: CDSOD323-T36SC)
D16  value 36V  [SOD-323-Bi]  (hidden comment: CDSOD323-T36SC)
L1  ValueDisplayed: 100µH  [WE-SPC_4838]  (hidden comment: 74408943101)
L2  ValueDisplayed: 100µH  [WE-SPC_4838]  (hidden comment: 74408943101)
L3  ValueDisplayed: 100µH  [WE-SPC_4838]  (hidden comment: 74408943101)
L4  ValueDisplayed: 100µH  [WE-SPC_4838]  (hidden comment: 74408943101)
R1  value 10.0  [0603]  (hidden comment: CRCW060310R0FKEA)
R2  value 10.0  [0603]  (hidden comment: CRCW060310R0FKEA)
R3  value 10.0  [0603]  (hidden comment: CRCW060310R0FKEA)
R4  value 10.0  [0603]  (hidden comment: CRCW060310R0FKEA)
R5  value 10.0  [0603]  (hidden comment: CRCW060310R0FKEA)
R6  value 10.0  [0603]  (hidden comment: CRCW060310R0FKEA)
R7  value 10.0  [0603]  (hidden comment: CRCW060310R0FKEA)
R8  value 10.0  [0603]  (hidden comment: CRCW060310R0FKEA)
R30  value 10.0  [0603]  (hidden comment: CRCW060310R0FKEA)
R31  value 10.0  [0603]  (hidden comment: CRCW060310R0FKEA)
R32  value 10.0  [0603]  (hidden comment: CRCW060310R0FKEA)
R33  value 10.0  [0603]  (hidden comment: CRCW060310R0FKEA)
R34  value 10.0  [0603]  (hidden comment: CRCW060310R0FKEA)
R35  value 10.0  [0603]  (hidden comment: CRCW060310R0FKEA)
R36  value 10.0  [0603]  (hidden comment: CRCW060310R0FKEA)
R37  value 10.0  [0603]  (hidden comment: CRCW060310R0FKEA)

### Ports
AGND_A (in), AGND_B (in), AGND_C (in), AGND_D (in), LN_A (bidir), LN_B (bidir), LN_C (bidir), LN_D (bidir), LP_A (bidir), LP_B (bidir), LP_C (bidir), LP_D (bidir), PVDD_A (in), PVDD_B (in), PVDD_C (in), PVDD_D (in), PVSS_A (in), PVSS_B (in), PVSS_C (in), PVSS_D (in), VNEG_IN_A (in), VNEG_IN_B (in), VNEG_IN_C (in), VNEG_IN_D (in), VPOS_IN_A (in), VPOS_IN_B (in), VPOS_IN_C (in), VPOS_IN_D (in)

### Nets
GND: C1.1 C2.2 C3.1 C4.2 C5.1 C6.2 C7.1 C8.2 C9.1 C10.2 C11.1 C12.2 C13.2 C14.2 C15.2 C16.2 C17.1 C18.2 C19.1 C20.2 C21.1 C22.2 C23.1 C24.2 C25.1 C26.2 C27.1 C28.2 C29.1 C30.2 C31.1 C32.2 C33.2 C34.2 C35.2 C36.2 C37.1 C38.2 C39.1 C40.2 D5.1 D6.1 D7.1 D8.1 D13.1 D14.1 D15.1 D16.1 ; port AGND_A, port PVSS_A, port AGND_B, port PVSS_B, port AGND_C, port PVSS_C, port AGND_D, port PVSS_D
PVDD/AVDD: C15.1 C16.1 C35.1 C36.1 ; port PVDD_A, port PVDD_B, port PVDD_C, port PVDD_D
VNEG_A: C6.1 C13.1 C18.1 D6.2 R2.1 R31.1 ; port VNEG_IN_A
VNEG_B: C8.1 C14.1 C20.1 D8.2 R4.1 R33.1 ; port VNEG_IN_B
VNEG_C: C26.1 C33.1 C38.1 D14.2 R6.1 R35.1 ; port VNEG_IN_C
VNEG_D: C28.1 C34.1 C40.1 D16.2 R8.1 R37.1 ; port VNEG_IN_D
VPOS_A: C5.2 C17.2 D5.2 R1.2 R30.1 ; port VPOS_IN_A
VPOS_B: C7.2 C19.2 D7.2 R3.2 R32.1 ; port VPOS_IN_B
VPOS_C: C25.2 C37.2 D13.2 R5.2 R34.1 ; port VPOS_IN_C
VPOS_D: C27.2 C39.2 D15.2 R7.2 R36.1 ; port VPOS_IN_D
LN_A: D1.2(A) L1.1 ; port LN_A
LN_B: D2.2(A) L2.1 ; port LN_B
LN_C: D9.2(A) L3.1 ; port LN_C
LN_D: D10.2(A) L4.1 ; port LN_D
LP_A: D3.1(K) L1.2 ; port LP_A
LP_B: D4.1(K) L2.2 ; port LP_B
LP_C: D11.1(K) L3.2 ; port LP_C
LP_D: D12.1(K) L4.2 ; port LP_D
NetC1_2: C1.2 D1.1(K) R30.2
NetC2_1: C2.1 D3.2(A) R31.2
NetC3_2: C3.2 D2.1(K) R32.2
NetC4_1: C4.1 D4.2(A) R33.2
NetC9_2: C9.2 R1.1
NetC10_1: C10.1 R2.2
NetC11_2: C11.2 R3.1
NetC12_1: C12.1 R4.2
NetC21_2: C21.2 D9.1(K) R34.2
NetC22_1: C22.1 D11.2(A) R35.2
NetC23_2: C23.2 D10.1(K) R36.2
NetC24_1: C24.1 D12.2(A) R37.2
NetC29_2: C29.2 R5.1
NetC30_1: C30.1 R6.2
NetC31_2: C31.2 R7.1
NetC32_1: C32.1 R8.2

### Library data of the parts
C1-C4 C15 C16 C21-C24 C35 C36 = UMK325AB7106KM-T: as C49 on sheet TIPD215_Device
C5-C8 C25-C28 = GRM188R71H104KA93D: as C41 on sheet TIPD215_Device
C9-C14 C17-C20 C29-C34 C37-C40 = UMK107AB7105KA-T: as C42 on sheet TIPD215_Device
D1-D4 D9-D12 = MBRX160-TP: Diode, Schottky, 60V, 1A, SOD-123; Manufacturer: Micro Commercial Components; U/M: EA; Vf_V: 0.72; Value2: 0.72V; Io_A: 1; Vr_V: 60; TJmax_C: 125
D5-D8 D13-D16 = CDSOD323-T36SC: as D19 on sheet TIPD215_Device
L1-L4 = 74408943101: Inductor, Shielded Drum Core, Ferrite, 100 µH, 0.52 A, 0.77 ohm, SMD; Manufacturer: Wurth Elektronik; Value: 100uH; Ind_H: 100.0E-6; Imax_A: 0.52; Irms: 0.52A @ 40C rise; Isat: 0.68A @ 35% inductance drop; DCR_ohm: 0.77; Value2: 0.52A; AEC Category: Q200
R1-R8 R30-R37 = CRCW060310R0FKEA: RES, 10.0 ohm, 1%, 0.1W, 0603; Manufacturer: Vishay-Dale; CompType: Resistor; Res_ohm: 10; Value_Code: 10R0; Tolerance_%: 1; Power_W: 0.1; VDC_V: 75; TempCo: 100 ppm/C; EIA_Code: E96; U/M: EA

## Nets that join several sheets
GND: TIPD215_Device (58 pins), TIPD215_DAC8775SMPS (48 pins)
PVDD/AVDD: TIPD215_Device (11 pins), TIPD215_DAC8775SMPS (C15.1 C16.1 C35.1 C36.1)
VNEG_A: TIPD215_Device (C53.2 D17.1 U1.19 U1.36), TIPD215_DAC8775SMPS (6 pins)
VNEG_B: TIPD215_Device (C55.2 D18.1 U1.20 U1.40), TIPD215_DAC8775SMPS (6 pins)
VNEG_C: TIPD215_Device (C63.2 D21.1 U1.51 U1.70), TIPD215_DAC8775SMPS (6 pins)
VNEG_D: TIPD215_Device (C65.2 D22.1 U1.55 U1.71), TIPD215_DAC8775SMPS (6 pins)
VPOS_A: TIPD215_Device (C52.2 D17.2 U1.38), TIPD215_DAC8775SMPS (5 pins)
VPOS_B: TIPD215_Device (C54.2 D18.2 U1.42), TIPD215_DAC8775SMPS (5 pins)
VPOS_C: TIPD215_Device (C62.2 D21.2 U1.49), TIPD215_DAC8775SMPS (5 pins)
VPOS_D: TIPD215_Device (C64.2 D22.2 U1.53), TIPD215_DAC8775SMPS (5 pins)
LN_A: TIPD215_Device (U1.14), TIPD215_DAC8775SMPS (D1.2 L1.1)
LN_B: TIPD215_Device (U1.10), TIPD215_DAC8775SMPS (D2.2 L2.1)
LN_C: TIPD215_Device (U1.8), TIPD215_DAC8775SMPS (D9.2 L3.1)
LN_D: TIPD215_Device (U1.4), TIPD215_DAC8775SMPS (D10.2 L4.1)
LP_A: TIPD215_Device (U1.16), TIPD215_DAC8775SMPS (D3.1 L1.2)
LP_B: TIPD215_Device (U1.12), TIPD215_DAC8775SMPS (D4.1 L2.2)
LP_C: TIPD215_Device (U1.6), TIPD215_DAC8775SMPS (D11.1 L3.2)
LP_D: TIPD215_Device (U1.2), TIPD215_DAC8775SMPS (D12.1 L4.2)

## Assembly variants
001: not fitted FID1 FID2 FID3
